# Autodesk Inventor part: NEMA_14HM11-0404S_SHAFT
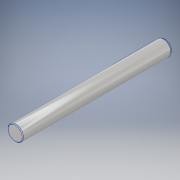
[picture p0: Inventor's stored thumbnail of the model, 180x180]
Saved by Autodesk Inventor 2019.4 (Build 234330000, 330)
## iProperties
Created: 2019-11
Part Number: NEMA_14HM11-0404S_SHAFT
Material: Générique
Document SubType Name: Modeling
Designer: thoma
Density: 1 g/cm^3
Appearance: Aluminium - Plat
Author: thoma
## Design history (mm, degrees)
sketch "Esquisse1"
  geometry: C1 r 2.5 at (0, 0); 1 further point
  constraints: 1 centre point, 1 coincident
  dimensions: "d0" = 5 diameter of C1
extrude "Extrusion1" new body sketch "Esquisse1" distance "d1" = 49; taper "d2" = 0 deg
chamfer "Chanfrein1" distance "d3" = 0.2; stored, may be unused: second distance "d4" = 2, angle "d5" = 45 deg
chamfer "Chanfrein2" distance "d6" = 0.3; stored, may be unused: second distance "d7" = 2, angle "d8" = 60 deg
sketch "Esquisse2"
  geometry: L1 (-2.5, 0)-(2, 0); L2 (2, 0)-(2, 1.5); L3 (2, 0)-(2, -1.5); A1 r 2.5 centre (0, 0) between (2, -1.5) and (2, 1.5); 2 further points
  constraints: 6 end point, 2 point on circle, 1 centre point, 1 coincident, 1 horizontal, 1 horizontal alignment, 1 point on line, 1 vertical, 1 other
  dimensions: "d9" = 4.5 distance of L1.start L1.end
extrude "Extrusion2" cut sketch "Esquisse2" distance "d10" = 15; taper "d11" = 0 deg
fillet "Congé1" dims "d12" = 0.1
node "Solide1"
